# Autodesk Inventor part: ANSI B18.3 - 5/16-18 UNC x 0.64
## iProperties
Created: 2005-06
Part Number: ANSI B18.3 - 5/16-18 UNC x 0.64
Vendor: Autodesk Inc.
Document SubType Name: Modeling
Designer: John Blackburn
Material: Default
Description: Hexagon Socket Set Screw - Half Dog Point
Standard: ANSI B18.3
Control State: 0
Master: False
Checked Out: False
Shininess: 64.0
Length Units: 11272
Angle Units: 11279
Time Units: 11290
Mass Units: 11286
Length Display Precision: 3
Angle Display Precision: 2
Compacted: True
EGR: 3
Classification: un/spsc 31161505
Density: 0.0
Volumn: 0.0
Area: 0.0
PropertySet Name: Model Information
Author: John Blackburn
Revision Number: 8
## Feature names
1. Body [Revolution]
2. Chamfer1
3. Slot [Extrusion]
4. Chamfer2
